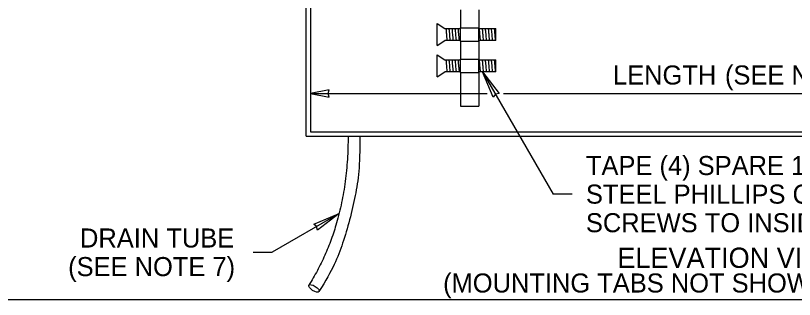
# Model space of a CAD drawing. Extents: x 99862 to 103680, y 99470 to 102076.
# Drawn here: x 101051 to 101706, y 100000 to 100238 of the extents above; entities that cross this region are included whole.
import ezdxf

# ---------------------------------------------------------------- set-up
doc = ezdxf.new("R2010")
doc.units = 0
for name, color, linetype in [('Level 1', 7, 'Continuous'), ('Level 10', 7, 'Continuous'), ('Level 14', 7, 'Continuous'), ('Level 15', 7, 'Continuous'), ('Level 20', 7, 'Continuous'), ('Level 7', 7, 'Continuous')]:
    doc.layers.add(name, color=color, linetype=linetype)

msp = doc.modelspace()

# ---------------------------------------------------------------- linework, layer by layer
at = {"layer": 'Level 1'}
for p, q in [((101295.35, 100136.47), (101295.35, 100500.54)), ((101298.92, 100400.54), (101298.92, 100140.04)), ((101298.92, 100140.04), (101330.63, 100140.04)), ((101330.63, 100140.04), (102011.78, 100140.04)), ((101295.35, 100136.47), (101330.63, 100136.47)), ((101330.63, 100136.47), (102015.35, 100136.47))]:
    msp.add_line(p, q, dxfattribs=at)
msp.add_lwpolyline([(99862, 99999.5), (103151, 99999.5), (103151, 102075.5), (99862, 102075.5)], close=True, dxfattribs=at)
msp.add_lwpolyline([(99862, 99999.5), (103151, 99999.5), (103151, 102075.5), (99862, 102075.5)], close=True, dxfattribs=at)
msp.add_lwpolyline([(99862, 99999.5), (103151, 99999.5), (103151, 102075.5), (99862, 102075.5)], close=True, dxfattribs=at)
at = {"layer": 'Level 10'}
for p, q in [((101405.4, 100212.69), (101405.4, 100231)), ((101405.4, 100231), (101411.85, 100226.84)), ((101411.85, 100226.84), (101424.99, 100226.84)), ((101440.46, 100226.84), (101454.9, 100226.84)), ((101454.9, 100216.84), (101454.9, 100226.84)), ((101405.4, 100212.69), (101411.85, 100216.84)), ((101424.99, 100216.84), (101411.85, 100216.84)), ((101454.9, 100216.84), (101440.46, 100216.84)), ((101405.4, 100186.45), (101405.4, 100204.76)), ((101405.4, 100204.76), (101411.85, 100200.61)), ((101411.85, 100200.61), (101424.99, 100200.61)), ((101440.46, 100200.61), (101454.9, 100200.61)), ((101454.9, 100190.61), (101454.9, 100200.61)), ((101405.4, 100186.45), (101411.85, 100190.61)), ((101424.99, 100190.61), (101411.85, 100190.61)), ((101454.9, 100190.61), (101440.46, 100190.61))]:
    msp.add_line(p, q, dxfattribs=at)
for points in [[(101414.15, 100216.84), (101414.09, 100216.93), (101413.95, 100217.48), (101413.72, 100219.69), (101413.46, 100223.23), (101413.22, 100225.88), (101413.06, 100226.68), (101413.01, 100226.83), (101413.01, 100226.84)], [(101416.68, 100216.84), (101416.64, 100216.9), (101416.56, 100217.16), (101416.38, 100218.37), (101416.14, 100221.25), (101415.9, 100224.39), (101415.7, 100226.19), (101415.6, 100226.7), (101415.54, 100226.84)], [(101419.22, 100216.84), (101419.21, 100216.86), (101419.1, 100217.08), (101418.92, 100218.36), (101418.7, 100220.99), (101418.51, 100223.45), (101418.32, 100225.64), (101418.17, 100226.61), (101418.09, 100226.83), (101418.08, 100226.84)], [(101421.76, 100216.84), (101421.72, 100216.89), (101421.61, 100217.23), (101421.46, 100218.46), (101421.27, 100220.66), (101421.07, 100223.18), (101420.85, 100225.71), (101420.7, 100226.64), (101420.62, 100226.84)], [(101424.29, 100216.84), (101424.26, 100216.89), (101424.13, 100217.31), (101423.92, 100219.15), (101423.66, 100222.54), (101423.44, 100225.19), (101423.27, 100226.46), (101423.19, 100226.76), (101423.16, 100226.84)], [(101442.06, 100216.84), (101442.03, 100216.89), (101441.92, 100217.23), (101441.76, 100218.46), (101441.57, 100220.66), (101441.38, 100223.18), (101441.15, 100225.71), (101441, 100226.64), (101440.92, 100226.84)], [(101444.6, 100216.84), (101444.57, 100216.89), (101444.43, 100217.31), (101444.23, 100219.15), (101443.96, 100222.54), (101443.75, 100225.19), (101443.57, 100226.46), (101443.49, 100226.76), (101443.46, 100226.84)], [(101447.14, 100216.84), (101447.1, 100216.89), (101447, 100217.23), (101446.84, 100218.46), (101446.62, 100220.93), (101446.43, 100223.51), (101446.21, 100225.8), (101446.09, 100226.61), (101446.01, 100226.83), (101446, 100226.84)], [(101449.68, 100216.84), (101449.62, 100216.93), (101449.49, 100217.5), (101449.26, 100219.69), (101448.99, 100223.23), (101448.75, 100225.88), (101448.6, 100226.68), (101448.55, 100226.83), (101448.54, 100226.84)], [(101452.21, 100216.84), (101452.18, 100216.89), (101452.07, 100217.23), (101451.89, 100218.65), (101451.7, 100220.99), (101451.48, 100223.76), (101451.28, 100225.95), (101451.13, 100226.7), (101451.08, 100226.84)], [(101454.76, 100216.84), (101454.7, 100216.93), (101454.56, 100217.48), (101454.34, 100219.69), (101454.07, 100223.23), (101453.83, 100225.88), (101453.68, 100226.68), (101453.62, 100226.83), (101453.62, 100226.84)], [(101414.15, 100190.61), (101414.09, 100190.69), (101413.95, 100191.25), (101413.72, 100193.45), (101413.46, 100196.99), (101413.22, 100199.65), (101413.06, 100200.44), (101413.01, 100200.59), (101413.01, 100200.61)], [(101416.68, 100190.61), (101416.64, 100190.66), (101416.56, 100190.92), (101416.38, 100192.14), (101416.14, 100195.02), (101415.9, 100198.16), (101415.7, 100199.95), (101415.6, 100200.47), (101415.54, 100200.61)], [(101419.22, 100190.61), (101419.21, 100190.62), (101419.1, 100190.85), (101418.92, 100192.12), (101418.7, 100194.75), (101418.51, 100197.22), (101418.32, 100199.41), (101418.17, 100200.37), (101418.09, 100200.59), (101418.08, 100200.61)], [(101421.76, 100190.61), (101421.72, 100190.66), (101421.61, 100191), (101421.46, 100192.22), (101421.27, 100194.42), (101421.07, 100196.94), (101420.85, 100199.47), (101420.7, 100200.4), (101420.62, 100200.61)], [(101424.29, 100190.61), (101424.26, 100190.66), (101424.13, 100191.08), (101423.92, 100192.91), (101423.66, 100196.31), (101423.44, 100198.96), (101423.27, 100200.23), (101423.19, 100200.53), (101423.16, 100200.61)], [(101442.06, 100190.61), (101442.03, 100190.66), (101441.92, 100191), (101441.76, 100192.22), (101441.57, 100194.42), (101441.38, 100196.94), (101441.15, 100199.47), (101441, 100200.4), (101440.92, 100200.61)], [(101444.6, 100190.61), (101444.57, 100190.66), (101444.43, 100191.08), (101444.23, 100192.91), (101443.96, 100196.31), (101443.75, 100198.96), (101443.57, 100200.23), (101443.49, 100200.53), (101443.46, 100200.61)], [(101447.14, 100190.61), (101447.1, 100190.66), (101447, 100191), (101446.84, 100192.22), (101446.62, 100194.7), (101446.43, 100197.28), (101446.21, 100199.56), (101446.09, 100200.38), (101446.01, 100200.59), (101446, 100200.61)], [(101449.68, 100190.61), (101449.62, 100190.7), (101449.49, 100191.27), (101449.26, 100193.46), (101448.99, 100196.99), (101448.75, 100199.65), (101448.6, 100200.44), (101448.55, 100200.59), (101448.54, 100200.61)], [(101452.21, 100190.61), (101452.18, 100190.66), (101452.07, 100191), (101451.89, 100192.41), (101451.7, 100194.75), (101451.48, 100197.52), (101451.28, 100199.72), (101451.13, 100200.47), (101451.08, 100200.61)], [(101454.76, 100190.61), (101454.7, 100190.69), (101454.56, 100191.25), (101454.34, 100193.45), (101454.07, 100196.99), (101453.83, 100199.65), (101453.68, 100200.44), (101453.62, 100200.59), (101453.62, 100200.61)]]:
    msp.add_open_spline(points, degree=3, dxfattribs=at)
at = {"layer": 'Level 14'}
msp.add_ellipse((101301.91, 100008.77), major_axis=(-4.23, 2.67), ratio=0.398386, dxfattribs=at)
for points, degree in [([(101330.63, 100136.47), (101330.63, 100063.69), (101297.68, 100011.44)], 2), ([(101340.63, 100136.47), (101340.63, 100111.46), (101337.8, 100088.04), (101326.33, 100044.51), (101317.68, 100024.41), (101306.14, 100006.1)], 3)]:
    msp.add_open_spline(points, degree=degree, dxfattribs=at)
at = {"layer": 'Level 15'}
for p, q in [((101443.69, 100190.61), (101502.99, 100087.89)), ((101298.92, 100172.24), (101447.37, 100172.24)), ((101461.22, 100172.24), (101889.97, 100172.24)), ((101518.99, 100087.89), (101502.99, 100087.89)), ((101323.09, 100071.54), (101266.8, 100039.04)), ((101250.8, 100039.04), (101266.8, 100039.04))]:
    msp.add_line(p, q, dxfattribs=at)
for points in [[(101443.69, 100190.61), (101457.69, 100172.33), (101454.58, 100171.75), (101452.52, 100169.34)], [(101298.92, 100172.24), (101314.64, 100169.15), (101313.91, 100172.24), (101314.64, 100175.32)], [(101323.09, 100071.54), (101304.81, 100057.54), (101304.23, 100060.66), (101301.83, 100062.71)]]:
    msp.add_lwpolyline(points, close=True, dxfattribs=at)
at = {"layer": 'Level 7'}
for p, q in [((101424.99, 100242.47), (101424.99, 100227.44)), ((101440.46, 100242.47), (101440.46, 100227.44)), ((101424.99, 100227.44), (101440.46, 100227.44)), ((101424.99, 100216.24), (101424.99, 100227.44)), ((101440.46, 100216.24), (101440.46, 100227.44)), ((101424.99, 100216.24), (101440.46, 100216.24)), ((101424.99, 100216.24), (101424.99, 100201.21)), ((101440.46, 100216.24), (101440.46, 100201.21)), ((101424.99, 100201.21), (101440.46, 100201.21)), ((101424.99, 100190.01), (101424.99, 100201.21)), ((101440.46, 100190.01), (101440.46, 100201.21)), ((101424.99, 100190.01), (101440.46, 100190.01)), ((101424.99, 100190.01), (101424.99, 100161.84)), ((101440.46, 100190.01), (101440.46, 100161.84)), ((101424.99, 100161.84), (101440.46, 100161.84))]:
    msp.add_line(p, q, dxfattribs=at)

# ---------------------------------------------------------------- texts
at = {"layer": 'Level 20'}
for s, height, p in [('LENGTH', 16, (101553.21, 100179.9)), (' (SEE NOTE 5)', 16, (101641.36, 100179.9)), ('TAPE (4) SPARE 1/4 - 20 × 1" (IN) STAINLESS', 16, (101530.47, 100103.89)), ('STEEL PHILLIPS COUNTERSUNK', 16, (101530.47, 100079.89)), ('SCREWS TO INSIDE OF BOX', 16, (101530.47, 100055.89)), ('DRAIN TUBE', 16, (101105.4, 100043.05)), ('ELEVATION VIEW', 17, (101556.87, 100025.97)), ('(SEE NOTE 7)', 16, (101095.42, 100019.05)), ('(MOUNTING TABS NOT SHOWN FOR CLARITY)', 16, (101410.46, 100005.28))]:
    msp.add_text(s, height=height, dxfattribs=at).set_placement(p)

doc.saveas('drawing.dxf')
